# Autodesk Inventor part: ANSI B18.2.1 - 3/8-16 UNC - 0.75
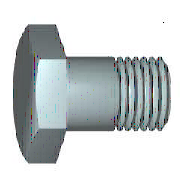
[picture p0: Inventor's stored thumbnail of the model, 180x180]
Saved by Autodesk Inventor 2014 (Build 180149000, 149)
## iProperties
IsCustomPart: 0
Created: 2008-02
Part Number: ANSI B18.2.1 - 3/8-16 UNC - 0.75
Material: Steel, Mild
Description: Hex Cap Screw
Document SubType Name: Modeling
Standard: ANSI B18.2.1
Designer: floress
Standard Revision: 1996
Standards Organization: ANSI
Language: en-US
Size Designation: 3/8-16 UNC - 0.75
Categories: <MemberInstance><Categories><Category DisplayName="Fasteners" InternalName="e4da775c-781d-43d5-af7c-5136215cf5a6" Mnemonic="FSTN"><Category DisplayName="Bolts"
Density: 7.86 g/cm^3
Mass: 18.5525 g
Surface Area: 11.7447 cm^2
Volume: 2.36038 cm^3
Appearance: Steel
Author: floress
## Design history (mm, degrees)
sketch "Sketch1"
  geometry: L1 (0, 6.429)-(0, 4.762); L2 (2.388, 4.762)-(19.05, 4.763); L3 (19.05, 4.763)-(19.05, 0); L4 (19.05, 0)-(-0.635, 0); L5 (-4.572, 0)-(22.987, 0) reference; L6 (-0.635, 0)-(-0.635, 6.429); L7 (-0.635, 6.429)-(0, 6.429); L8 (2.388, 4.762)-(0.8, 4.762); L9 (0.8, 4.762)-(0, 4.762); L10 (0, -1.286)-(0, 7.715) reference
  constraints: 16 end point, 2 collinear, 2 perpendicular, 1 parallel
  dimensions: "d0" = 19.05 distance between parallel lines of L3 L1 (= NLG); "d1" = 16.6624 distance from line of L2.start L3 (= GEL); "d2" = 9.525 diameter of L2 L4 (= GD); "d9" = 0.6351 distance between parallel lines of L6 L1 (computed from SD); "d10" = 12.85875 diameter of L7 L4 (= SD2); "d13" = 1.5876 distance of L2.start L8.end (computed from GAL); "d14" = 9.525 diameter of L9 L4 (= BDM)
revolve "Body" sketch "Sketch1" stored, may be unused: angle "d12" = 90 deg
sketch "Sketch2"
  geometry: L1 (0, 8.249)-(7.144, 4.124); L2 (7.144, 4.124)-(7.144, -4.124); L3 (7.144, -4.124)-(0, -8.249); L4 (0, -8.249)-(-7.144, -4.124); L5 (-7.144, -4.124)-(-7.144, 4.124); L6 (-7.144, 4.124)-(0, 8.249); 2 further points
  constraints: 12 end point, 1 coincident, 1 vertical, 11 other
  dimensions: "d11" = 14.2875 distance between parallel lines of L5 L2 (= SW)
extrude "Head" join sketch "Sketch2" distance "d3" = 5.31813 (= KOH - SD); taper "d4" = 0 deg
sketch "Sketch4"
  geometry: L1 (-5.953, 7.144)-(-5.953, 8.249); L2 (-5.953, 8.249)-(-5.315, 8.249); L3 (-5.315, 8.249)-(-5.953, 7.144); L4 (-7.017, 0)-(0.429, 0) reference; L5 (-0.635, 8.249)-(-5.953, 8.249) reference; L6 (-5.953, 4.124)-(-5.953, 8.249) reference
  constraints: 6 end point, 2 collinear, 1 perpendicular, 1 vertical
  dimensions: "d5" = 30 deg angle of L3 L1 (= ANG1); "d19" = 14.2875 diameter of L1.start L4 (= SW0)
revolve "Chamfer1" sketch "Sketch4" stored, may be unused: angle "d21" = 90 deg
workplane "Work Plane1"
fillet "Fillet2" dims "d63" = 0.635 (= R)
body "Solid1"
feature "Thread" dims "d15" = 16.6624 (= GEL), "d16" = 0
chamfer "Chamfer2" distance "d6" = 0.85928 (= -0.5 x SPD + 0.5 x GD); stored, may be unused: second distance "d7" = 1.5876 (computed from GUL), angle "d55" = 45 deg
other parameters: "NLG" = 19.05 [user parameter; used in 2 equation terms], "GD" = 9.525 (= NND) [user parameter; used in 2 equation terms], "BDM" = 9.525 [user parameter; used in 1 equation term], "KOH" = 5.95312 [user parameter; used in 1 equation term], "GEL" = 16.6624 [user parameter; used in 2 equation terms], "SW" = 14.2875 [user parameter; used in 3 equation terms], "SW0" = 14.2875 (= SW) [user parameter; used in 1 equation term], "SPD" = 7.80644 (= GD1) [user parameter; used in 1 equation term], "SD2" = 12.85875 [user parameter; used in 1 equation term], "SD" = 0.635 [user parameter; used in 3 equation terms], "ANG1" = 30 deg [user parameter; used in 1 equation term], "GAL" = 1.5875 [user parameter; used in 1 equation term], "GUL" = 1.5875 [user parameter; used in 2 equation terms], "d8" = 0, "R" = 0.635 [user parameter; used in 1 equation term], "d58" = 0, "d62" = -18.0975 (= -NLG - SD + GUL), "THREADDIA" = 9.525 [user parameter], "TOA" = 30 deg [user parameter], "RR" = 0.508 [user parameter], "PTC" = 1.5875 (computed from TPU) [user parameter], "NND" = 9.525 [user parameter; used in 1 equation term], "E0" = 16.50206 (= 1.155 x SW) [user parameter], "SLG" = 0 [user parameter], "GD1" = 7.80644 [user parameter; used in 1 equation term]
